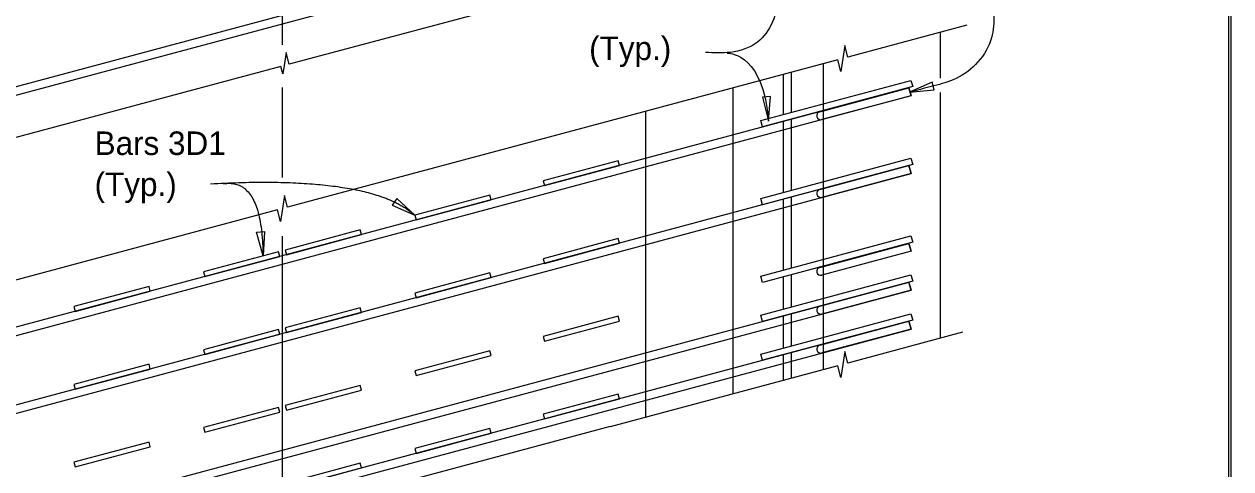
# Model space of a CAD drawing. Extents: x 0 to 30.8, y 0 to 19.8.
# Drawn here: x 23.04 to 30.8, y 9.58 to 12.43 of the extents above; entities that cross this region are included whole.
import ezdxf

# ---------------------------------------------------------------- set-up
doc = ezdxf.new("R2010")
doc.units = 0
for name, color, linetype in [('ActivePts-ConstElements', 7, 'Continuous'), ('BeamConc', 7, 'Continuous'), ('BeamConc_h', 7, 'Continuous'), ('CL_Major', 7, 'Continuous'), ('Dimension', 7, 'Continuous'), ('Miscellaneous1', 7, 'Continuous'), ('Rebar', 7, 'Continuous'), ('Rebar_h', 7, 'Continuous')]:
    doc.layers.add(name, color=color, linetype=linetype)

msp = doc.modelspace()

# ---------------------------------------------------------------- linework, layer by layer
at = {"layer": 'ActivePts-ConstElements'}
msp.add_lwpolyline([(0, 0), (30.7879, 0), (30.7879, 19.4596), (0, 19.4596)], close=True, dxfattribs=at)
at = {"layer": 'BeamConc'}
for p, q in [((28.9316, 12.3825), (28.9316, 12.087)), ((27.5982, 12.0253), (27.5982, 10.0587)), ((28.9316, 11.9958), (28.9316, 10.4159))]:
    msp.add_line(p, q, dxfattribs=at)
at = {"layer": 'BeamConc_h'}
for p, q in [((28.1816, 10.215), (28.1816, 12.1816)), ((27.0357, 11.8746), (27.0357, 9.908))]:
    msp.add_line(p, q, dxfattribs=at)
at = {"layer": 'CL_Major'}
for p, q in [((24.7024, 12.3022), (24.7024, 17.2351)), ((24.7024, 11.448), (24.7024, 12.0271)), ((24.7024, 9.5072), (24.7024, 11.0727))]:
    msp.add_line(p, q, dxfattribs=at)
at = {"layer": 'Dimension'}
for points in [[(26.7823, 12.7225), (24.7454, 12.1769), (24.7254, 12.2517), (24.7129, 12.1682), (24.705, 12.1159)], [(29.103, 12.4284), (28.3372, 12.2232), (28.3172, 12.298), (28.3047, 12.2145), (28.2919, 12.1308), (28.2719, 12.2057), (26.8097, 11.814)], [(24.705, 12.1159), (24.6925, 12.1626), (21.9874, 11.438)], [(26.8097, 11.8141), (24.7349, 11.2583), (24.7149, 11.3331), (24.7024, 11.2496), (24.6897, 11.1659), (24.6697, 11.2408), (22.6484, 10.6994)], [(29.0742, 10.4541), (28.3372, 10.2566), (28.3172, 10.3314), (28.3047, 10.2479), (28.2919, 10.1642), (28.2719, 10.2391), (26.8097, 9.8474)], [(26.8097, 9.8475), (24.7349, 9.2917), (24.7149, 9.3665), (24.7024, 9.283), (24.6897, 9.1993), (24.6697, 9.2742), (22.6484, 8.7328)]]:
    msp.add_lwpolyline(points, dxfattribs=at)
for points in [[(28.7346, 11.9965), (28.8922, 12.0115), (28.8785, 12.0626)], [(27.8279, 11.8116), (27.8404, 11.9695), (27.7877, 11.9648)], [(25.5528, 11.206), (25.4376, 11.3148), (25.4082, 11.2708)], [(24.5771, 10.9446), (24.534, 11.097), (24.5866, 11.1027)]]:
    msp.add_lwpolyline(points, close=True, dxfattribs=at)
for points in [[(27.8175, 13.3385), (27.8991, 12.6161), (27.7554, 12.3186), (27.5822, 12.2533), (27.4221, 12.2533)], [(29.4186, 12.8346), (29.3435, 12.8346), (29.2553, 12.7724), (29.2553, 12.645), (29.2553, 12.3279), (29.1573, 12.1743), (29.0136, 12.0763), (28.8731, 12.0338), (28.7346, 11.9964)]]:
    msp.add_spline(points, degree=3, dxfattribs=at)
for points, degree in [([(27.5618, 12.2477), (27.597, 12.2461), (27.7905, 12.2314), (27.8279, 11.8116)], 3), ([(24.2392, 11.4086), (25.2732, 11.4648), (25.5528, 11.2061)], 2), ([(24.3232, 11.4086), (24.5714, 11.4493), (24.5771, 10.9447)], 2)]:
    msp.add_open_spline(points, degree=degree, dxfattribs=at)
at = {"layer": 'Miscellaneous1'}
msp.add_lwpolyline([(0, 19.8), (30.8, 19.8), (30.8, 0), (0, 0)], close=True, dxfattribs=at)
at = {"layer": 'Rebar'}
for p, q in [((27.9212, 12.1118), (27.9212, 11.8529)), ((27.9732, 12.1258), (27.9732, 11.8669)), ((27.7773, 11.8144), (28.7433, 12.0732)), ((28.7541, 12.0329), (27.7881, 11.7741)), ((28.7433, 12.0732), (28.7541, 12.0329)), ((28.1565, 11.8714), (28.7302, 12.0252)), ((28.7437, 11.9748), (28.17, 11.8211)), ((28.7302, 12.0252), (28.7437, 11.9748)), ((27.7881, 11.7741), (27.7773, 11.8144)), ((27.9212, 11.8097), (27.9212, 11.3529)), ((27.9732, 11.8237), (27.9732, 11.3669)), ((27.7773, 11.3144), (28.7433, 11.5732)), ((28.7433, 11.5732), (28.7541, 11.5329)), ((28.7541, 11.5329), (27.7881, 11.2741)), ((28.1565, 11.3714), (28.7302, 11.5252)), ((28.7302, 11.5252), (28.7437, 11.4748)), ((28.7437, 11.4748), (28.17, 11.3211)), ((27.7881, 11.2741), (27.7773, 11.3144)), ((27.9212, 11.3097), (27.9212, 10.8529)), ((27.9732, 11.3237), (27.9732, 10.8669)), ((27.7773, 10.8144), (28.7433, 11.0732)), ((28.7541, 11.0329), (27.7881, 10.7741)), ((28.1565, 10.8714), (28.7302, 11.0252)), ((28.7302, 11.0252), (28.7437, 10.9748)), ((28.7433, 11.0732), (28.7541, 11.0329)), ((28.7437, 10.9748), (28.17, 10.8211)), ((27.7773, 10.5644), (28.7433, 10.8232)), ((27.7881, 10.7741), (27.7773, 10.8144)), ((27.9212, 10.8097), (27.9212, 10.6029)), ((27.9732, 10.8237), (27.9732, 10.6169)), ((28.7433, 10.8232), (28.7541, 10.7829)), ((28.7541, 10.7829), (27.7881, 10.5241)), ((28.1565, 10.6214), (28.7302, 10.7752)), ((28.7437, 10.7248), (28.17, 10.5711)), ((28.7302, 10.7752), (28.7437, 10.7248)), ((27.7773, 10.3144), (28.7433, 10.5732)), ((27.7881, 10.5241), (27.7773, 10.5644)), ((27.9212, 10.5597), (27.9212, 10.3529)), ((27.9732, 10.5737), (27.9732, 10.3669)), ((28.7433, 10.5732), (28.7541, 10.5329)), ((28.7541, 10.5329), (27.7881, 10.2741)), ((28.1565, 10.3714), (28.7302, 10.5252)), ((28.7437, 10.4748), (28.17, 10.3211)), ((28.7302, 10.5252), (28.7437, 10.4748)), ((27.9732, 10.3237), (27.9732, 10.1591)), ((27.7881, 10.2741), (27.7773, 10.3144)), ((27.9212, 10.3097), (27.9212, 10.1452))]:
    msp.add_line(p, q, dxfattribs=at)
for points in [[(26.3861, 11.397), (26.8691, 11.5264), (26.861, 11.5566), (26.378, 11.4272)], [(25.5609, 11.1759), (26.0438, 11.3053), (26.0357, 11.3355), (25.5528, 11.2061)], [(24.7275, 10.9526), (25.2105, 11.082), (25.2024, 11.1122), (24.7194, 10.9828)], [(26.3861, 10.897), (26.8691, 11.0264), (26.861, 11.0566), (26.378, 10.9272)], [(24.2024, 10.8119), (24.6854, 10.9413), (24.6773, 10.9715), (24.1943, 10.8421)], [(25.5609, 10.6759), (26.0438, 10.8053), (26.0357, 10.8355), (25.5528, 10.7061)], [(23.3691, 10.5886), (23.852, 10.718), (23.8439, 10.7482), (23.361, 10.6188)], [(24.7275, 10.4526), (25.2105, 10.582), (25.2024, 10.6122), (24.7194, 10.4828)], [(26.3861, 10.397), (26.8691, 10.5264), (26.861, 10.5566), (26.378, 10.4272)], [(24.2024, 10.3119), (24.6854, 10.4413), (24.6773, 10.4715), (24.1943, 10.3421)], [(25.5609, 10.1759), (26.0438, 10.3053), (26.0357, 10.3355), (25.5528, 10.2061)], [(23.3691, 10.0886), (23.852, 10.218), (23.8439, 10.2482), (23.361, 10.1188)], [(24.7275, 9.9526), (25.2105, 10.082), (25.2024, 10.1122), (24.7194, 9.9828)], [(26.3861, 9.897), (26.8691, 10.0264), (26.861, 10.0566), (26.378, 9.9272)], [(24.2024, 9.8119), (24.6854, 9.9413), (24.6773, 9.9715), (24.1943, 9.8421)], [(25.5609, 9.6759), (26.0438, 9.8053), (26.0357, 9.8355), (25.5528, 9.7061)], [(23.3691, 9.5886), (23.852, 9.718), (23.8439, 9.7482), (23.361, 9.6188)], [(24.7275, 9.4526), (25.2105, 9.582), (25.2024, 9.6122), (24.7194, 9.4828)]]:
    msp.add_lwpolyline(points, close=True, dxfattribs=at)
for centre in [(28.1632, 11.8463), (28.1632, 11.3463), (28.1632, 10.8463), (28.1632, 10.5963), (28.1632, 10.3463)]:
    msp.add_arc(centre, 0.026, 105, 285, dxfattribs=at)
at = {"layer": 'Rebar_h'}
msp.add_line((28.7437, 10.9749), (28.7302, 11.0251), dxfattribs=at)
for points in [[(28.7407, 13.5739), (20.6513, 11.4064), (20.6648, 11.3562), (28.7541, 13.5237)], [(28.7302, 12.0251), (20.6513, 9.8604), (20.6648, 9.8101), (28.7437, 11.9749)], [(28.7302, 11.5251), (20.6513, 9.3604), (20.6648, 9.3101), (28.7437, 11.4749)], [(28.7302, 10.7751), (20.6513, 8.6104), (20.6648, 8.5601), (28.7437, 10.7249)], [(28.7302, 10.5251), (20.6513, 8.3604), (20.6648, 8.3101), (28.7437, 10.4749)]]:
    msp.add_lwpolyline(points, close=True, dxfattribs=at)

# ---------------------------------------------------------------- texts
at = {"layer": 'Dimension'}
for s, p in [('(Typ.)', (26.6738, 12.2038)), ('Bars 3D1 ', (23.4942, 11.5935)), ('(Typ.)', (23.4942, 11.3295))]:
    msp.add_text(s, height=0.1512, dxfattribs=at).set_placement(p)

doc.saveas('drawing.dxf')
